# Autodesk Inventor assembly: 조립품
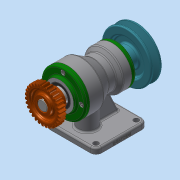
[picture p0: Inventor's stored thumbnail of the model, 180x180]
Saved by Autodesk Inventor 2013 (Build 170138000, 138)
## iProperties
Created: 2019-01
Part Number: 조립품
Document SubType Name: Assembly
Designer: dgall
Author: dgall
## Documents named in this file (15)
- C:\Users\dgall\Desktop\490107V1048\조립품.iam
- C:\Users\dgall\Desktop\490107V1048\본체.ipt
- C:\Users\dgall\Desktop\490107V1048\축.ipt
- C:\Users\dgall\Desktop\490107V1048\베어링 6203.ipt
- C:\Users\dgall\Desktop\490107V1048\베어링 6205.ipt
- C:\Users\dgall\Desktop\490107V1048\뒤커버.ipt
- C:\Users\dgall\Desktop\490107V1048\앞커버.ipt
- C:\Users\dgall\Desktop\490107V1048\오일 실 17 30 8.ipt
- C:\Users\dgall\Desktop\490107V1048\오일 실 25 38 8.ipt
- C:\Users\dgall\Desktop\490107V1048\키 6 x 6 x 18.ipt
- C:\Users\dgall\Desktop\490107V1048\키 5 x 5 x 20.ipt
- C:\Users\dgall\Desktop\490107V1048\멈춤나사 M3.ipt
- C:\Users\dgall\Desktop\490107V1048\V-벨트풀리.ipt
- C:\Users\dgall\Desktop\490107V1048\스퍼기어.ipt
- C:\Users\dgall\Desktop\490107V1048\볼트 M4.ipt
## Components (1 placed, 1 different names)
1. V-벨트풀리:1
